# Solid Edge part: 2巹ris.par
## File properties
Author: Egon 815
Template: Normal.par
Last saved by: Egon 815
Revision: 3
Application: Solid Edge
Accuracy: 0,990
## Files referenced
..\Laev.asm
.C:\Kool\3D Modelleerimine\LaevaJoonis\Laev.asm
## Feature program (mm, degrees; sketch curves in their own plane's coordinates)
swept protrusion "unnamed SweptProtrusion 1"
sketch for "ExtrudedCutout_1" plane through (0, 0, 0) normal (0, -1, 0) x-axis (1, 0, 0)
  line (-505.6603, 10061.9525) -> (0, 10061.9525)
  line (0, 10061.9525) -> (0, 7403.5458)
  line (0, 7403.5458) -> (-505.6603, 7403.5458)
  line (-505.6603, 7403.5458) -> (-505.6603, 10061.9525)
extrude "ExtrudedCutout_1" cut finite along +normal
sketch for "ExtrudedCutout_3" plane through (0, 0, 0) normal (1, 0, 0) x-axis (0, 1, 0)
  line (-68880.7154, 7725.7223) -> (-68880.7154, 5526.0068)
  line (-68880.7154, 5526.0068) -> (-67880.7154, 5526.0068)
  line (-67880.7154, 5526.0068) -> (-67880.7154, 7225.7223)
  line (-67880.7154, 7225.7223) -> (-67880.7154, 7725.7223)
  line (-67880.7154, 7725.7223) -> (-68880.7154, 7725.7223)
extrude "ExtrudedCutout_3" cut finite 32664.9317 along +normal
pattern "unnamed Pattern 1" of "ExtrudedCutout_3"
extrude "unnamed Cutout 1" cut finite 32664.9317
extrude "unnamed Cutout 2" cut finite 32664.9317
extrude "unnamed Cutout 3" cut finite 32664.9317
extrude "unnamed Cutout 4" cut finite 32664.9317
extrude "unnamed Cutout 5" cut finite 32664.9317
extrude "unnamed Cutout 6" cut finite 32664.9317
extrude "unnamed Cutout 7" cut finite 32664.9317
extrude "unnamed Cutout 8" cut finite 32664.9317
extrude "unnamed Cutout 9" cut finite 32664.9317
swept protrusion "unnamed SweptProtrusion 2"
chamfer "Chamfer_1" setback 100
body pattern "unnamed BodyPattern 1"
pattern "unnamed Pattern 2"
Other named dimensions: "ExtrudedSurface_2": FiniteDepth = 33203.8058 mm
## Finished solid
Body 1: solid body, 112 faces, 306 edges, 196 vertices.
  Faces by surface: plane 98, spline 14
  Edges by curve: intersection 132, line 118, spline 56
Body 2: sheet body, 2 faces, 7 edges, 6 vertices.
  Faces by surface: plane 2
  Edges by curve: line 7
Body 3: sheet body, 9 faces, 27 edges, 18 vertices.
  Faces by surface: plane 5, swept 4
  Edges by curve: line 19, spline 6, ellipse 2
Bounding box of the edges (mm; curved faces can reach further): 33203.806 x 52881.206 x 9087.462, from (-16601.9029, -111592.4206, 2356.269) to (16601.9029, -58711.2146, 11443.731).
Planar faces by outward normal: +y 20, +z 2, -y 20, -z 20, oblique 36
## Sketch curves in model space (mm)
line (0, -70214.464, 10786.5296) -> (0, -70214.464, 10761.1296)
line (0, -70239.864, 10786.5296) -> (0, -70214.464, 10786.5296)
line (0, -70239.864, 10761.1296) -> (0, -70239.864, 10786.5296)
line (0, -70214.464, 10761.1296) -> (0, -70239.864, 10761.1296)
line (0, -67880.7154, 7725.7223) -> (0, -68880.7154, 7725.7223)
line (0, -68880.7154, 7725.7223) -> (0, -68880.7154, 5526.0068)
line (0, -68880.7154, 5526.0068) -> (0, -67880.7154, 5526.0068)
line (0, -67880.7154, 5526.0068) -> (0, -67880.7154, 7225.7223)
line (0, -67880.7154, 7225.7223) -> (0, -67880.7154, 7725.7223)
line (0, 0, 7403.5458) -> (-505.6603, 0, 7403.5458)
line (-505.6603, 0, 7403.5458) -> (-505.6603, 0, 10061.9525)
line (-505.6603, 0, 10061.9525) -> (0, 0, 10061.9525)
line (0, 0, 10061.9525) -> (0, 0, 7403.5458)
line (10274.5263, -66219.9057, 8184.526) -> (10215.4605, -66211.0713, 8184.526)
line (10215.4605, -66211.0713, 8184.526) -> (10211.8051, -66235.5113, 7184.6106)
line (10211.8051, -66235.5113, 7184.6106) -> (10270.8716, -66244.3403, 7184.8312)
line (10270.8716, -66244.3403, 7184.8312) -> (10274.5263, -66219.9057, 8184.526)
spline (447.1879, -111271.2026, 6900) -> (6989.2589, -89283.5525, 6900) -> (10270.8716, -66244.3403, 6900)
spline (0, -111592.4206, 6900) -> (221.1794, -111446.1369, 6900) -> (447.1879, -111271.2026, 6900)
ellipse centre (13709.6016, 247493.0857, 6900) radii 359679.9473, 27758.8062 from (-447.1878, -111271.2026, 6900) through (-224.0695, -111444.0636, 6900) to (0, -111592.4206, 6900)
spline (-447.1878, -111271.2026, 6900) -> (-6989.2589, -89283.5525, 6900) -> (-10270.8716, -66244.3403, 6900)
line (-10270.8716, -66244.3403, 6900) -> (-11107.5407, -59431.1311, 6900)
line (-11087.1817, -58711.2146, 6900) -> (-11107.5407, -59431.1311, 6900)
line (-11087.1817, -58711.2146, 6900) -> (11087.1817, -58711.2146, 6900)
line (11087.1817, -58711.2146, 6900) -> (11107.5407, -59431.1311, 6900)
line (11107.5407, -59431.1311, 6900) -> (10270.8716, -66244.3403, 6900)
line (0, -55258.6238, 6900) -> (0, -66153.1161, 6900)
line (0, -111271.2026, 8310) -> (0, -111592.4206, 8310)
line (0, -111271.2026, 8310) -> (0, -66244.3403, 7184.8312)
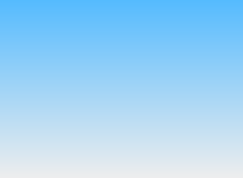
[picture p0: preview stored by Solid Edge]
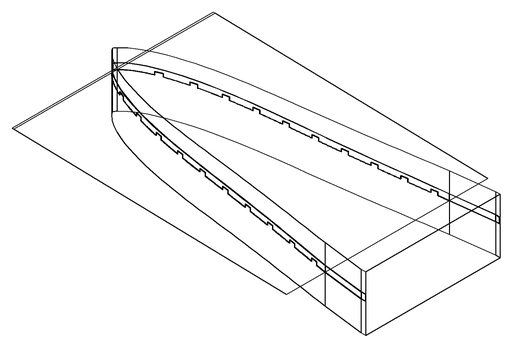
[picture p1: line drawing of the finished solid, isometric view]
